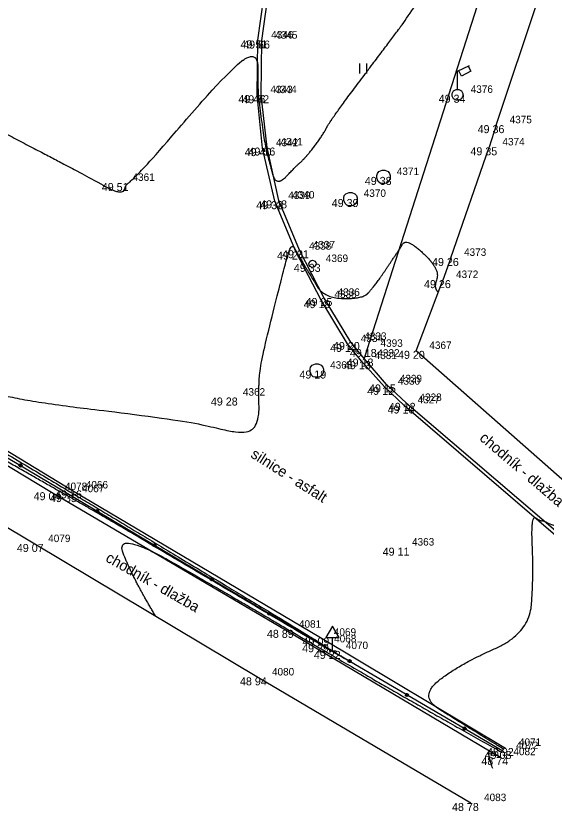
# Model space of a CAD drawing. Extents: x -704017 to -701500, y -1008977 to -1008450.
# Drawn here: x -701739.51 to -701719.63, y -1008977.27 to -1008947.47 of the extents above; entities that cross this region are included whole.
import ezdxf

# ---------------------------------------------------------------- set-up
doc = ezdxf.new("R2010")
doc.units = 0
for name, color, linetype in [('Z_body', 7, 'Continuous'), ('Z_body_cisla', 7, 'Continuous'), ('Z_body_vysky', 7, 'Continuous'), ('Z_budovy', 7, 'Continuous'), ('Z_chodnik', 7, 'Continuous'), ('Z_dopravni_znaceni', 7, 'Continuous'), ('Z_komunikace', 7, 'Continuous'), ('Z_obruby', 7, 'Continuous'), ('Z_popis', 7, 'Continuous'), ('Z_rozhrani_ploch', 7, 'Continuous'), ('Z_site_znaky_kanalizace', 7, 'Continuous'), ('Z_site_znaky_plynovod', 7, 'Continuous'), ('Z_site_znaky_VO', 7, 'Continuous'), ('Z_vrstevnice_hlavni', 7, 'Continuous'), ('Z_vrstevnice_vedlejsi', 7, 'Continuous'), ('Z_vstupy', 7, 'Continuous'), ('Z_zabradli', 7, 'Continuous')]:
    doc.layers.add(name, color=color, linetype=linetype)

# ---------------------------------------------------------------- blocks, each defined once
blk = doc.blocks.new('POINT_DISPLAY')
blk.add_line((0, 0), (0, 0))
blk = doc.blocks.new('Z530')
for p, q in [((-0.05, 0.03), (-0.03, 0.05)), ((-0.05, -0.03), (-0.05, 0.03)), ((-0.03, 0.05), (0.03, 0.05)), ((-0.03, -0.03), (-0.03, 0.03)), ((-0.03, 0.03), (0.03, 0.03)), ((-0.03, -0.03), (0.03, 0.03)), ((0.03, 0.05), (0.05, 0.03)), ((0.03, 0.03), (0.03, -0.03)), ((0.05, 0.03), (0.05, -0.03)), ((-0.03, -0.05), (-0.05, -0.03)), ((0.03, -0.03), (-0.03, -0.03)), ((0.03, -0.05), (-0.03, -0.05)), ((0.05, -0.03), (0.03, -0.05))]:
    blk.add_line(p, q)
blk = doc.blocks.new('Z306')
for p, q in [((-0.13, 0.17), (-0.13, -0.2)), ((0.13, 0.17), (0.13, -0.2))]:
    blk.add_line(p, q)
blk = doc.blocks.new('Z13')
for p, q in [((0, 0.88), (0.45, 1.1)), ((0.15, 0.7), (0.05, 0.9)), ((0.4, 1.07), (0.5, 0.88)), ((0, 0.2), (0, 0.88)), ((0.5, 0.88), (0.15, 0.7)), ((-0.2, 0.05), (-0.15, 0.15)), ((-0.2, -0.05), (-0.2, 0.05)), ((-0.15, 0.15), (-0.05, 0.2)), ((-0.05, 0.2), (0.05, 0.2)), ((0.05, 0.2), (0.15, 0.15)), ((0.15, 0.15), (0.2, 0.05)), ((0.2, 0.05), (0.2, -0.05)), ((-0.15, -0.15), (-0.2, -0.05)), ((-0.05, -0.2), (-0.15, -0.15)), ((0.05, -0.2), (-0.05, -0.2)), ((0.15, -0.15), (0.05, -0.2)), ((0.2, -0.05), (0.15, -0.15))]:
    blk.add_line(p, q)
blk = doc.blocks.new('Z527')
for p, q in [((0, 0.93), (-0.25, 0.5)), ((0.25, 0.5), (0, 0.93)), ((-0.25, 0.5), (0.25, 0.5)), ((0, 0), (0, 0.5)), ((-0.13, 0), (0.13, 0))]:
    blk.add_line(p, q)
blk = doc.blocks.new('Z620')
for p, q in [((-0.25, 0.05), (-0.23, 0.13)), ((-0.25, -0.05), (-0.25, 0.05)), ((-0.23, 0.13), (-0.17, 0.2)), ((-0.17, 0.2), (-0.05, 0.25)), ((-0.05, 0.25), (0.05, 0.25)), ((0.05, 0.25), (0.17, 0.2)), ((0.17, 0.2), (0.23, 0.13)), ((0.23, 0.13), (0.25, 0.05)), ((0.25, 0.05), (0.25, -0.05)), ((-0.2, -0.17), (-0.25, -0.05)), ((-0.13, -0.23), (-0.2, -0.17)), ((-0.05, -0.25), (-0.13, -0.23)), ((0.05, -0.25), (-0.05, -0.25)), ((0.13, -0.23), (0.05, -0.25)), ((0.2, -0.17), (0.13, -0.23)), ((0.25, -0.05), (0.2, -0.17))]:
    blk.add_line(p, q)
blk = doc.blocks.new('Z614')
for p, q in [((-0.13, 0.03), (-0.1, 0.08)), ((-0.13, -0.03), (-0.13, 0.03)), ((-0.1, 0.08), (-0.08, 0.1)), ((-0.08, 0.1), (-0.03, 0.13)), ((-0.03, 0.13), (0.03, 0.13)), ((0.03, 0.13), (0.08, 0.1)), ((0.08, 0.1), (0.1, 0.08)), ((0.1, 0.08), (0.13, 0.03)), ((0.13, 0.03), (0.13, -0.03)), ((-0.1, -0.08), (-0.13, -0.03)), ((-0.08, -0.1), (-0.1, -0.08)), ((-0.03, -0.13), (-0.08, -0.1)), ((0.03, -0.13), (-0.03, -0.13)), ((0.08, -0.1), (0.03, -0.13)), ((0.1, -0.08), (0.08, -0.1)), ((0.13, -0.03), (0.1, -0.08))]:
    blk.add_line(p, q)

msp = doc.modelspace()

# ---------------------------------------------------------------- linework, layer by layer
at = {"layer": 'Z_budovy'}
for p, q in [((-701721.5, -1008951.56), (-701719.32, -1008945.02)), ((-701723.21, -1008956.54), (-701721.77, -1008952.39)), ((-701724.51, -1008960.02), (-701723.51, -1008957.37)), ((-701715.73, -1008967.75), (-701724.51, -1008960.02))]:
    msp.add_line(p, q, dxfattribs=at)
at = {"layer": 'Z_chodnik'}
for p, q in [((-701722.1, -1008946.73), (-701726.34, -1008959.95)), ((-701726.34, -1008959.95), (-701726.46, -1008960.31)), ((-701744.26, -1008964.01), (-701738.8, -1008967.26)), ((-701738.8, -1008967.26), (-701730.41, -1008972.26)), ((-701730.41, -1008972.26), (-701722.46, -1008976.97))]:
    msp.add_line(p, q, dxfattribs=at)
at = {"layer": 'Z_komunikace'}
for p, q in [((-701730.44, -1008948.38), (-701730.17, -1008946.4)), ((-701730.47, -1008950.43), (-701730.44, -1008948.38)), ((-701730.26, -1008952.42), (-701730.47, -1008950.43)), ((-701729.8, -1008954.41), (-701730.26, -1008952.42)), ((-701729.02, -1008956.3), (-701729.8, -1008954.41)), ((-701728.07, -1008958.12), (-701729.02, -1008956.3)), ((-701727.08, -1008959.76), (-701728.07, -1008958.12)), ((-701726.56, -1008960.41), (-701727.08, -1008959.76)), ((-701725.69, -1008961.37), (-701726.56, -1008960.41)), ((-701744.67, -1008960.85), (-701737.39, -1008965.25)), ((-701724.95, -1008962.07), (-701725.69, -1008961.37)), ((-701716.88, -1008969.01), (-701724.95, -1008962.07)), ((-701737.39, -1008965.25), (-701728.09, -1008970.77)), ((-701728.09, -1008970.77), (-701721.15, -1008974.91))]:
    msp.add_line(p, q, dxfattribs=at)
at = {"layer": 'Z_obruby'}
for p, q in [((-701730.29, -1008948.39), (-701730.02, -1008946.43)), ((-701730.32, -1008950.44), (-701730.29, -1008948.39)), ((-701730.09, -1008952.4), (-701730.32, -1008950.44)), ((-701729.65, -1008954.38), (-701730.09, -1008952.4)), ((-701728.88, -1008956.25), (-701729.65, -1008954.38)), ((-701727.95, -1008958.04), (-701728.88, -1008956.25)), ((-701726.95, -1008959.69), (-701727.95, -1008958.04)), ((-701726.46, -1008960.31), (-701726.95, -1008959.69)), ((-701725.62, -1008961.28), (-701726.46, -1008960.31)), ((-701724.88, -1008961.97), (-701725.62, -1008961.28)), ((-701724.88, -1008961.97), (-701716.77, -1008968.91))]:
    msp.add_line(p, q, dxfattribs=at)
at = {"layer": 'Z_rozhrani_ploch'}
for p, q in [((-701744.94, -1008961.26), (-701738.17, -1008965.32)), ((-701738.17, -1008965.32), (-701729.4, -1008970.48)), ((-701729.4, -1008970.48), (-701721.36, -1008975.25))]:
    msp.add_line(p, q, dxfattribs=at)
at = {"layer": 'Z_vrstevnice_hlavni'}
for points in [[(-701721.205, -1008974.965), (-701722.881, -1008973.939), (-701724.416, -1008972.962), (-701722.838, -1008971.748), (-701720.254, -1008970.612), (-701720.1, -1008968.384), (-701720.203, -1008966.152), (-701719.827, -1008966.416), (-701719.758, -1008966.353), (-701716.042, -1008968.098)], [(-701734.282, -1008969.952), (-701735.144, -1008968.512), (-701735.831, -1008966.696), (-701731.344, -1008969.263), (-701729.037, -1008970.629), (-701724.537, -1008973.25), (-701721.284, -1008975.074)]]:
    msp.add_open_spline(points, degree=2, dxfattribs=at)
at = {"layer": 'Z_vrstevnice_vedlejsi'}
for points in [[(-701773.971, -1008959.221), (-701773.611, -1008958.899), (-701768.633, -1008950.858), (-701768.32, -1008950.374), (-701768.26, -1008950.536), (-701767.757, -1008950.395), (-701767.625, -1008950.96), (-701767.096, -1008950.484), (-701765.713, -1008950.612), (-701763.054, -1008947.869), (-701762.897, -1008947.613), (-701762.622, -1008947.644), (-701762.63, -1008947.61), (-701762.506, -1008947.635), (-701760.8, -1008947.99), (-701759.208, -1008948.143), (-701758.947, -1008948.041), (-701758.388, -1008948.143), (-701758.235, -1008948.241), (-701751.691, -1008949.254), (-701747.637, -1008948.233), (-701746.394, -1008948.75), (-701743.001, -1008950.306), (-701742.288, -1008950.624), (-701736.747, -1008953.52), (-701735.858, -1008954.034), (-701735.46, -1008954.08), (-701735.395, -1008953.825), (-701735.333, -1008953.766), (-701735.151, -1008953.611), (-701734.606, -1008953.07), (-701731.409, -1008949.369), (-701730.446, -1008948.79), (-701730.434, -1008950.022), (-701730.433, -1008950.432), (-701730.287, -1008951.52), (-701730.154, -1008952.408), (-701730.018, -1008952.903), (-701729.76, -1008953.885), (-701728.989, -1008953.081), (-701728.637, -1008952.767), (-701728.025, -1008951.97), (-701727.684, -1008951.31), (-701724.593, -1008947.235), (-701724.318, -1008946.646), (-701723.939, -1008946.078), (-701722.809, -1008944.781), (-701722.509, -1008944.53), (-701721.936, -1008943.957), (-701721.659, -1008943.897), (-701721.075, -1008943.473), (-701720.79, -1008943.82), (-701719.4, -1008944.98)], [(-701769.616, -1008962.465), (-701767.944, -1008960.809), (-701765.414, -1008959.18), (-701762.009, -1008957.985), (-701757.483, -1008957.16), (-701757.399, -1008956.341), (-701757.328, -1008956.208), (-701751.702, -1008955.174), (-701750.924, -1008954.743), (-701750.62, -1008954.578), (-701749.783, -1008954.69), (-701746.89, -1008955.5), (-701744.604, -1008956.622), (-701741.739, -1008960.56), (-701741.413, -1008960.996), (-701740.237, -1008961.789), (-701732.973, -1008962.64), (-701730.962, -1008963.191), (-701730.381, -1008962.764), (-701730.41, -1008961.433), (-701730.357, -1008960.553), (-701729.64, -1008957.668), (-701729.265, -1008956.205), (-701729.118, -1008956.064), (-701729.046, -1008956.22), (-701729, -1008956.293), (-701728.475, -1008957.185), (-701727.95, -1008958.04), (-701726.55, -1008958.077), (-701726.127, -1008957.693), (-701725.153, -1008956.248), (-701724.861, -1008955.781), (-701723.601, -1008956.966), (-701723.864, -1008957.693), (-701723.677, -1008957.812)], [(-701744.685, -1008960.942), (-701744.868, -1008961.224), (-701741.036, -1008963.496), (-701737.736, -1008965.367), (-701735.763, -1008966.497), (-701728.212, -1008970.966), (-701727.591, -1008971.328), (-701726.781, -1008971.782), (-701727.829, -1008971.163), (-701728.082, -1008970.97), (-701733.899, -1008967.459), (-701737.456, -1008965.316), (-701741.723, -1008962.777), (-701743.961, -1008961.42), (-701744.685, -1008960.942)], [(-701721.635, -1008975.68), (-701721.896, -1008974.932), (-701721.482, -1008975.173), (-701721.357, -1008975.243)]]:
    msp.add_open_spline(points, degree=2, dxfattribs=at)
at = {"layer": 'Z_vstupy'}
for p, q in [((-701721.5, -1008951.56), (-701721.77, -1008952.39)), ((-701723.21, -1008956.54), (-701723.51, -1008957.37))]:
    msp.add_line(p, q, dxfattribs=at)
at = {"layer": 'Z_zabradli'}
for p, q in [((-701744.72, -1008961.15), (-701737.53, -1008965.39)), ((-701737.53, -1008965.39), (-701728.08, -1008971.02)), ((-701728.08, -1008971.02), (-701721.26, -1008975.02))]:
    msp.add_line(p, q, dxfattribs=at)

# ---------------------------------------------------------------- block references
at = {"layer": 'Z_body'}
for p in [(-701730.44, -1008948.38), (-701730.29, -1008948.39), (-701730.47, -1008950.43), (-701722.96, -1008950.42), (-701730.32, -1008950.44), (-701721.5, -1008951.56), (-701730.26, -1008952.42), (-701730.09, -1008952.4), (-701721.77, -1008952.39), (-701725.73, -1008953.5), (-701735.64, -1008953.73), (-701729.8, -1008954.41), (-701729.65, -1008954.38), (-701726.97, -1008954.33), (-701729.02, -1008956.3), (-701728.88, -1008956.25), (-701723.21, -1008956.54), (-701728.39, -1008956.76), (-701723.51, -1008957.37), (-701728.07, -1008958.12), (-701727.95, -1008958.04), (-701727.08, -1008959.76), (-701726.95, -1008959.69), (-701726.34, -1008959.95), (-701724.51, -1008960.02), (-701726.56, -1008960.41), (-701726.46, -1008960.31), (-701728.23, -1008960.76), (-701725.69, -1008961.37), (-701725.62, -1008961.28), (-701731.5, -1008961.77), (-701724.88, -1008961.97), (-701724.95, -1008962.07), (-701738.17, -1008965.32), (-701737.39, -1008965.25), (-701737.53, -1008965.39), (-701738.8, -1008967.26), (-701725.16, -1008967.4), (-701729.4, -1008970.48), (-701728.09, -1008970.77), (-701728.08, -1008971.02), (-701727.64, -1008971.27), (-701730.41, -1008972.26), (-701721.26, -1008975.02), (-701721.15, -1008974.91), (-701721.36, -1008975.25), (-701722.46, -1008976.97)]:
    msp.add_blockref('POINT_DISPLAY', p, dxfattribs=at)
at = {"layer": 'Z_dopravni_znaceni'}
msp.add_blockref('Z527', (-701727.64, -1008971.27), dxfattribs=at)
at = {"layer": 'Z_popis'}
msp.add_blockref('Z306', (-701726.5, -1008949.42), dxfattribs=at)
at = {"layer": 'Z_site_znaky_kanalizace'}
for p in [(-701725.73, -1008953.5), (-701726.97, -1008954.33), (-701728.23, -1008960.76)]:
    msp.add_blockref('Z620', p, dxfattribs=at)
at = {"layer": 'Z_site_znaky_plynovod', "rotation": 10.799999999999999}
msp.add_blockref('Z614', (-701728.39, -1008956.76), dxfattribs=at)
at = {"layer": 'Z_site_znaky_VO'}
msp.add_blockref('Z13', (-701722.96, -1008950.42), dxfattribs=at)
at = {"layer": 'Z_zabradli'}
for p, rotation in [((-701739.34, -1008964.32), 149.5), ((-701736.46, -1008966.03), 149.2), ((-701734.31, -1008967.31), 149.2), ((-701732.16, -1008968.59), 149.2), ((-701730.01, -1008969.87), 149.2), ((-701727, -1008971.65), 149.6), ((-701724.85, -1008972.92), 149.6), ((-701722.69, -1008974.18), 149.6)]:
    msp.add_blockref('Z530', p, dxfattribs=dict(at, rotation=rotation))

# ---------------------------------------------------------------- texts
at = {"layer": 'Z_body_cisla'}
for s, p in [('4346', (-701729.94, -1008948.31)), ('4345', (-701729.79, -1008948.32)), ('4343', (-701729.97, -1008950.36)), ('4344', (-701729.82, -1008950.36)), ('4376', (-701722.46, -1008950.35)), ('4375', (-701721, -1008951.49)), ('4342', (-701729.76, -1008952.35)), ('4341', (-701729.59, -1008952.32)), ('4374', (-701721.27, -1008952.32)), ('4361', (-701735.14, -1008953.65)), ('4371', (-701725.23, -1008953.43)), ('4370', (-701726.47, -1008954.25)), ('4339', (-701729.3, -1008954.33)), ('4340', (-701729.15, -1008954.31)), ('4338', (-701728.52, -1008956.23)), ('4337', (-701728.38, -1008956.18)), ('4373', (-701722.71, -1008956.46)), ('4369', (-701727.89, -1008956.69)), ('4372', (-701723.01, -1008957.29)), ('4335', (-701727.57, -1008958.04)), ('4336', (-701727.45, -1008957.96)), ('4333', (-701726.45, -1008959.61)), ('4334', (-701726.58, -1008959.69)), ('4393', (-701725.84, -1008959.87)), ('4367', (-701724.01, -1008959.95)), ('4332', (-701725.96, -1008960.24)), ('4331', (-701726.06, -1008960.33)), ('4368', (-701727.73, -1008960.69)), ('4330', (-701725.19, -1008961.29)), ('4329', (-701725.12, -1008961.2)), ('4362', (-701731, -1008961.7)), ('4327', (-701724.45, -1008961.99)), ('4328', (-701724.38, -1008961.9)), ('4078', (-701737.67, -1008965.24)), ('4067', (-701737.03, -1008965.32)), ('4066', (-701736.89, -1008965.18)), ('4079', (-701738.3, -1008967.19)), ('4363', (-701724.66, -1008967.32)), ('4081', (-701728.9, -1008970.4)), ('4069', (-701727.59, -1008970.7)), ('4068', (-701727.58, -1008970.95)), ('4070', (-701727.14, -1008971.2)), ('4080', (-701729.91, -1008972.19)), ('4071', (-701720.65, -1008974.83)), ('4072', (-701720.76, -1008974.95)), ('4082', (-701720.86, -1008975.18)), ('4083', (-701721.96, -1008976.9))]:
    msp.add_text(s, height=0.28, dxfattribs=at).set_placement(p)
at = {"layer": 'Z_body_vysky'}
for s, p in [('49 51', (-701731.09, -1008948.68)), ('49 66', (-701730.99, -1008948.69)), ('49 46', (-701731.17, -1008950.73)), ('49 62', (-701731.02, -1008950.74)), ('49 34', (-701723.66, -1008950.72)), ('49 36', (-701722.2, -1008951.86)), ('49 40', (-701730.935, -1008952.72)), ('49 56', (-701730.79, -1008952.7)), ('49 35', (-701722.47, -1008952.69)), ('49 38', (-701726.43, -1008953.8)), ('49 51', (-701736.29, -1008954.03)), ('49 32', (-701730.5, -1008954.71)), ('49 48', (-701730.35, -1008954.68)), ('49 39', (-701727.67, -1008954.63)), ('49 24', (-701729.72, -1008956.6)), ('49 31', (-701729.53, -1008956.55)), ('49 26', (-701723.91, -1008956.84)), ('49 33', (-701729.09, -1008957.06)), ('49 26', (-701724.21, -1008957.67)), ('49 19', (-701728.72, -1008958.42)), ('49 25', (-701728.65, -1008958.34)), ('49 14', (-701727.73, -1008960.06)), ('49 20', (-701727.625, -1008959.99)), ('49 18', (-701726.99, -1008960.25)), ('49 20', (-701725.185, -1008960.32)), ('49 13', (-701727.21, -1008960.71)), ('49 18', (-701727.11, -1008960.61)), ('49 19', (-701728.88, -1008961.06)), ('49 12', (-701726.34, -1008961.67)), ('49 15', (-701726.27, -1008961.58)), ('49 28', (-701732.2, -1008962.07)), ('49 12', (-701725.53, -1008962.27)), ('49 10', (-701725.575, -1008962.37)), ('49 04', (-701738.845, -1008965.62)), ('49 16', (-701738.04, -1008965.55)), ('49 35', (-701738.23, -1008965.69)), ('49 07', (-701739.475, -1008967.56)), ('49 11', (-701725.76, -1008967.7)), ('48 89', (-701730.1, -1008970.78)), ('49 09', (-701728.765, -1008971.07)), ('49 29', (-701728.78, -1008971.32)), ('49 22', (-701728.34, -1008971.57)), ('48 94', (-701731.11, -1008972.56)), ('49 08', (-701721.935, -1008975.32)), ('48 92', (-701721.85, -1008975.21)), ('48 74', (-701722.06, -1008975.55)), ('48 78', (-701723.16, -1008977.27))]:
    msp.add_text(s, height=0.3, dxfattribs=at).set_placement(p)
at = {"layer": 'Z_popis'}
for s, rotation, p in [('chodník - dlažba', 319.5, (-701722.16, -1008963.34)), ('silnice - asfalt', 327.6, (-701730.74, -1008963.99)), ('chodník - dlažba', 330.3, (-701736.18, -1008967.89))]:
    msp.add_text(s, height=0.4, rotation=rotation, dxfattribs=at).set_placement(p)

doc.saveas('drawing.dxf')
